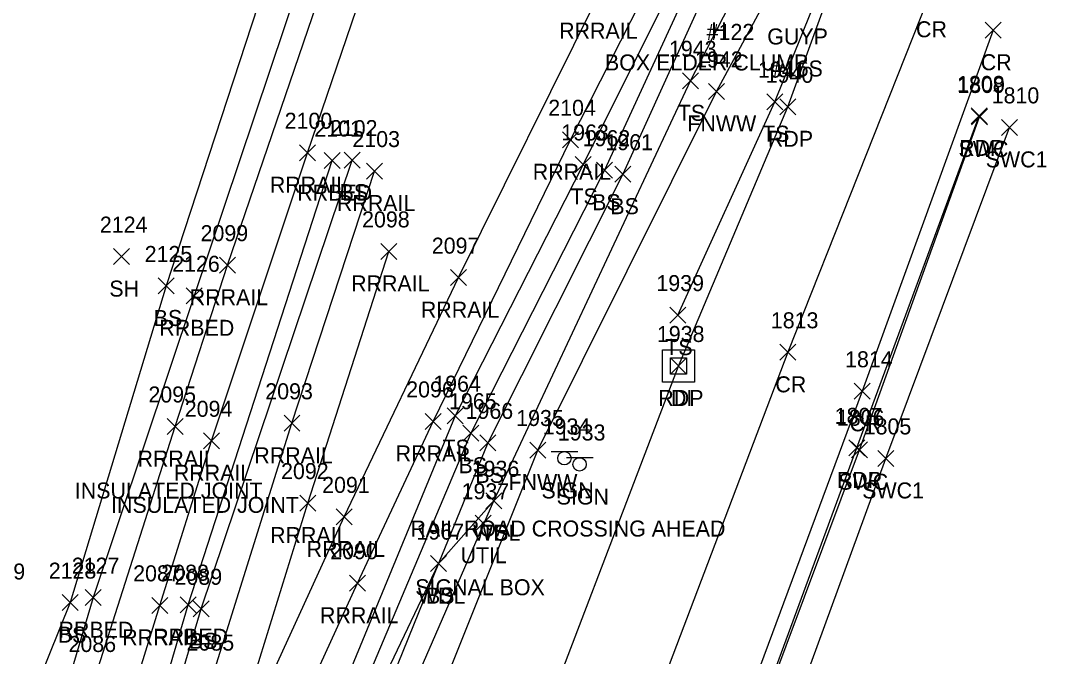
# Model space of a CAD drawing. Extents: x 1769141 to 1770817, y 735471 to 742405.
# Drawn here: x 1770272.6 to 1770400.9, y 742233 to 742312.5 of the extents above; entities that cross this region are included whole.
import ezdxf

# ---------------------------------------------------------------- set-up
doc = ezdxf.new("R2010")
doc.units = 0
for name, color, linetype in [('D_A', 7, 'Continuous'), ('D_I', 7, 'Continuous'), ('DS', 7, 'Continuous'), ('L_A', 7, 'Continuous'), ('L_C', 7, 'Continuous'), ('L_I', 7, 'Continuous'), ('L_TIC', 7, 'Continuous'), ('LAWA', 7, 'Continuous'), ('LELB', 7, 'Continuous'), ('LFNC', 7, 'Continuous'), ('P_A', 7, 'Continuous'), ('P_I', 7, 'Continuous'), ('P_TIC', 7, 'Continuous'), ('PET', 7, 'Continuous'), ('PRC', 7, 'Continuous'), ('R_A', 7, 'Continuous'), ('R_C', 7, 'Continuous'), ('R_I', 7, 'Continuous'), ('R_TIC', 7, 'Continuous'), ('RR', 7, 'Continuous'), ('RRB', 7, 'Continuous'), ('RSW', 7, 'Continuous'), ('S_A', 7, 'Continuous'), ('S_C', 7, 'Continuous'), ('S_I', 7, 'Continuous'), ('SSGN', 7, 'Continuous'), ('U_A', 7, 'Continuous'), ('U_C', 7, 'Continuous'), ('U_I', 7, 'Continuous'), ('UDEFAULT', 7, 'Continuous')]:
    doc.layers.add(name, color=color, linetype=linetype)

msp = doc.modelspace()

# ---------------------------------------------------------------- linework, layer by layer
at = {"layer": 'DS'}
for p, q in [((1770352.85, 742271.34), (1770356.85, 742271.34)), ((1770352.85, 742267.34), (1770352.85, 742271.34)), ((1770356.85, 742271.34), (1770356.85, 742267.34)), ((1770353.85, 742268.34), (1770353.85, 742270.34)), ((1770353.85, 742270.34), (1770355.85, 742270.34)), ((1770355.85, 742270.34), (1770355.85, 742268.34)), ((1770354.85, 742269.34), (1770354.85, 742269.34)), ((1770354.85, 742269.34), (1770354.85, 742269.34)), ((1770356.85, 742267.34), (1770352.85, 742267.34)), ((1770355.85, 742268.34), (1770353.85, 742268.34))]:
    msp.add_line(p, q, dxfattribs=at)
at = {"layer": 'L_TIC'}
for points in [[(1770355.36, 742303.98), (1770357.36, 742305.98)], [(1770357.36, 742303.98), (1770355.36, 742305.98)], [(1770358.62, 742302.65), (1770360.62, 742304.65)], [(1770360.62, 742302.65), (1770358.62, 742304.65)], [(1770365.91, 742301.37), (1770367.91, 742303.37)], [(1770367.91, 742301.37), (1770365.91, 742303.37)], [(1770313.05, 742294.07), (1770315.05, 742296.07)], [(1770315.05, 742294.07), (1770313.05, 742296.07)], [(1770341.94, 742293.53), (1770343.94, 742295.53)], [(1770343.94, 742293.53), (1770341.94, 742295.53)], [(1770344.62, 742292.81), (1770346.62, 742294.81)], [(1770346.62, 742292.81), (1770344.62, 742294.81)], [(1770346.9, 742292.31), (1770348.9, 742294.31)], [(1770348.9, 742292.31), (1770346.9, 742294.31)], [(1770284.21, 742282.01), (1770286.21, 742284.01)], [(1770286.21, 742282.01), (1770284.21, 742284.01)], [(1770289.81, 742278.34), (1770291.81, 742280.34)], [(1770291.81, 742278.34), (1770289.81, 742280.34)], [(1770353.8, 742274.7), (1770355.8, 742276.7)], [(1770355.8, 742274.7), (1770353.8, 742276.7)], [(1770325.94, 742262.13), (1770327.94, 742264.13)], [(1770327.94, 742262.13), (1770325.94, 742264.13)], [(1770327.91, 742259.94), (1770329.91, 742261.94)], [(1770329.91, 742259.94), (1770327.91, 742261.94)], [(1770330.03, 742258.73), (1770332.03, 742260.73)], [(1770332.03, 742258.73), (1770330.03, 742260.73)], [(1770336.26, 742257.84), (1770338.26, 742259.84)], [(1770338.26, 742257.84), (1770336.26, 742259.84)], [(1770330.76, 742251.5), (1770332.76, 742253.5)], [(1770332.76, 742251.5), (1770330.76, 742253.5)], [(1770330.76, 742251.5), (1770332.76, 742253.5)], [(1770332.76, 742251.5), (1770330.76, 742253.5)], [(1770323.85, 742243.64), (1770325.85, 742245.64)], [(1770325.85, 742243.64), (1770323.85, 742245.64)], [(1770323.85, 742243.64), (1770325.85, 742245.64)], [(1770325.85, 742243.64), (1770323.85, 742245.64)], [(1770277.82, 742238.77), (1770279.82, 742240.77)], [(1770279.82, 742238.77), (1770277.82, 742240.77)], [(1770294.2, 742238), (1770296.2, 742240)], [(1770296.2, 742238), (1770294.2, 742240)]]:
    msp.add_lwpolyline(points, dxfattribs=at)
at = {"layer": 'LAWA'}
msp.add_lwpolyline([(1770278.27, 742098.51), (1770292.63, 742130.75), (1770300.5, 742163.1), (1770310.78, 742196.92), (1770318.92, 742223), (1770331.76, 742252.5), (1770324.85, 742244.64), (1770302.11, 742188.56), (1770291.13, 742150.41), (1770288.91, 742136.29), (1770280.1, 742115.2), (1770273.51, 742098.5)], dxfattribs=at)
at = {"layer": 'LELB'}
for points in [[(1770332.23, 742396.99), (1770317.41, 742358.29), (1770305.3, 742323.67), (1770290.81, 742279.34), (1770278.82, 742239.77), (1770261.32, 742196.43), (1770254.37, 742156.7), (1770242.09, 742122.31), (1770234.14, 742089.37), (1770227.06, 742053.39), (1770219.68, 742019.63), (1770213.36, 741989.97), (1770210.16, 741976.3), (1770206.14, 741961.98)], [(1770380.12, 742366.91), (1770363.06, 742334.87), (1770342.94, 742294.53), (1770326.94, 742263.13), (1770309.84, 742221.71), (1770298.92, 742189.88), (1770289.69, 742167.82), (1770287.13, 742167.67), (1770285.1, 742161.65), (1770288.13, 742159.66), (1770284.67, 742135.52), (1770276.3, 742117.05), (1770269.66, 742099.09), (1770260.58, 742066.82), (1770250.33, 742031.54), (1770242.02, 742000.43), (1770236.09, 741978.68), (1770232.48, 741959.64)], [(1770381.35, 742366.29), (1770364.19, 742334.21), (1770345.62, 742293.81), (1770328.91, 742260.94), (1770312.07, 742221.07), (1770300.68, 742188.95), (1770290.98, 742164.79), (1770288.07, 742165.78), (1770286.6, 742162.38), (1770289.46, 742160.5), (1770286.3, 742134.62), (1770278.73, 742116.17), (1770272.1, 742098.75), (1770262.82, 742065.76), (1770253.59, 742031.78), (1770244.44, 742003.2), (1770237.54, 741978.15), (1770232.48, 741959.64)], [(1770383.19, 742365.59), (1770366.14, 742333.56), (1770347.9, 742293.31), (1770331.03, 742259.73), (1770324.85, 742244.64), (1770313.21, 742220.31)], [(1770331.76, 742252.5), (1770356.36, 742304.98), (1770372.15, 742335.65), (1770385.81, 742364.15)], [(1770354.8, 742275.7), (1770366.91, 742302.37), (1770378.08, 742330.08), (1770389.36, 742362.55)], [(1770255.17, 742093.88), (1770277.55, 742179.23), (1770295.2, 742239), (1770314.05, 742295.07)]]:
    msp.add_lwpolyline(points, dxfattribs=at)
at = {"layer": 'LFNC'}
msp.add_lwpolyline([(1770315.95, 742200.26), (1770321.95, 742220.54), (1770337.26, 742258.84), (1770359.62, 742303.65), (1770374.37, 742330.92)], dxfattribs=at)
at = {"layer": 'P_TIC'}
for points in [[(1770393.22, 742310.3), (1770395.22, 742312.3)], [(1770395.22, 742310.3), (1770393.22, 742312.3)], [(1770367.55, 742300.73), (1770369.55, 742302.73)], [(1770369.55, 742300.73), (1770367.55, 742302.73)], [(1770391.46, 742299.59), (1770393.46, 742301.59)], [(1770393.46, 742299.59), (1770391.46, 742301.59)], [(1770367.53, 742270.05), (1770369.53, 742272.05)], [(1770369.53, 742270.05), (1770367.53, 742272.05)], [(1770353.85, 742268.34), (1770355.85, 742270.34)], [(1770355.85, 742268.34), (1770353.85, 742270.34)], [(1770376.82, 742265.18), (1770378.82, 742267.18)], [(1770378.82, 742265.18), (1770376.82, 742267.18)], [(1770376.16, 742258.11), (1770378.16, 742260.11)], [(1770378.16, 742258.11), (1770376.16, 742260.11)]]:
    msp.add_lwpolyline(points, dxfattribs=at)
at = {"layer": 'PET'}
for points in [[(1770272.7, 742023.54), (1770282.64, 742061.02), (1770293.57, 742093.79), (1770304.4, 742127.71), (1770313.88, 742157.38), (1770333.72, 742213.99), (1770354.85, 742269.34), (1770368.55, 742301.73), (1770378.75, 742329.81), (1770392.05, 742361.37)], [(1770296.04, 742015.55), (1770303.14, 742042.61), (1770312.37, 742074.12), (1770317.15, 742087.84), (1770319.53, 742093.81), (1770328.4, 742119.72), (1770345.72, 742170.91), (1770359.21, 742210.32), (1770377.16, 742259.11), (1770392.46, 742300.59)]]:
    msp.add_lwpolyline(points, dxfattribs=at)
at = {"layer": 'PRC'}
for points in [[(1770386.13, 742315.42), (1770368.53, 742271.05), (1770352, 742227.48), (1770338.73, 742191.59), (1770324.94, 742150.68), (1770312.78, 742113.37), (1770302.28, 742081.69), (1770292.17, 742047.68), (1770283.01, 742015.74), (1770275.68, 741981.9), (1770269.49, 741954.54), (1770264.41, 741931.75), (1770261.81, 741920.34)], [(1770394.22, 742311.3), (1770377.82, 742266.18), (1770362.64, 742225.34), (1770348.95, 742186.97), (1770334.4, 742149.35), (1770325.02, 742114.58)]]:
    msp.add_lwpolyline(points, dxfattribs=at)
at = {"layer": 'R_TIC'}
for points in [[(1770391.51, 742299.46), (1770393.51, 742301.46)], [(1770393.51, 742299.46), (1770391.51, 742301.46)], [(1770395.24, 742298.16), (1770397.24, 742300.16)], [(1770397.24, 742298.16), (1770395.24, 742300.16)], [(1770340.35, 742296.61), (1770342.35, 742298.61)], [(1770342.35, 742296.61), (1770340.35, 742298.61)], [(1770307.47, 742294.99), (1770309.47, 742296.99)], [(1770309.47, 742294.99), (1770307.47, 742296.99)], [(1770310.55, 742294.01), (1770312.55, 742296.01)], [(1770312.55, 742294.01), (1770310.55, 742296.01)], [(1770315.86, 742292.7), (1770317.86, 742294.7)], [(1770317.86, 742292.7), (1770315.86, 742294.7)], [(1770317.64, 742282.66), (1770319.64, 742284.66)], [(1770319.64, 742282.66), (1770317.64, 742284.66)], [(1770297.46, 742280.94), (1770299.46, 742282.94)], [(1770299.46, 742280.94), (1770297.46, 742282.94)], [(1770326.36, 742279.38), (1770328.36, 742281.38)], [(1770328.36, 742279.38), (1770326.36, 742281.38)], [(1770293.31, 742277.11), (1770295.31, 742279.11)], [(1770295.31, 742277.11), (1770293.31, 742279.11)], [(1770323.21, 742261.42), (1770325.21, 742263.42)], [(1770325.21, 742261.42), (1770323.21, 742263.42)], [(1770290.93, 742260.78), (1770292.93, 742262.78)], [(1770292.93, 742260.78), (1770290.93, 742262.78)], [(1770305.54, 742261.18), (1770307.54, 742263.18)], [(1770307.54, 742261.18), (1770305.54, 742263.18)], [(1770295.47, 742258.99), (1770297.47, 742260.99)], [(1770297.47, 742258.99), (1770295.47, 742260.99)], [(1770376.48, 742257.88), (1770378.48, 742259.88)], [(1770378.48, 742257.88), (1770376.48, 742259.88)], [(1770379.8, 742256.79), (1770381.8, 742258.79)], [(1770381.8, 742256.79), (1770379.8, 742258.79)], [(1770307.51, 742251.21), (1770309.51, 742253.21)], [(1770309.51, 742251.21), (1770307.51, 742253.21)], [(1770312.08, 742249.48), (1770314.08, 742251.48)], [(1770314.08, 742249.48), (1770312.08, 742251.48)], [(1770313.75, 742241.2), (1770315.75, 742243.2)], [(1770315.75, 742241.2), (1770313.75, 742243.2)], [(1770280.7, 742239.39), (1770282.7, 742241.39)], [(1770282.7, 742239.39), (1770280.7, 742241.39)], [(1770289.02, 742238.43), (1770291.02, 742240.43)], [(1770291.02, 742238.43), (1770289.02, 742240.43)], [(1770292.54, 742238.51), (1770294.54, 742240.51)], [(1770294.54, 742238.51), (1770292.54, 742240.51)]]:
    msp.add_lwpolyline(points, dxfattribs=at)
at = {"layer": 'RR'}
for points in [[(1770228.86, 742035.21), (1770233.42, 742054.72), (1770238.03, 742073.49), (1770247.64, 742110.86), (1770257.95, 742148.59), (1770267.65, 742182.8), (1770278.27, 742218.42), (1770281.99, 742230.6), (1770291.93, 742261.78), (1770298.46, 742281.94), (1770310.78, 742317.95), (1770323.27, 742353.88), (1770336.53, 742389.56)], [(1770271.65, 742142.74), (1770276.09, 742158.59), (1770294.25, 742208.74), (1770297.09, 742215.37), (1770299.29, 742220.45), (1770313.08, 742250.48), (1770327.36, 742280.38), (1770344.65, 742315.25), (1770362.7, 742349.81), (1770381.95, 742383.73)], [(1770234.04, 742035.58), (1770238.5, 742054.13), (1770247.99, 742091.95), (1770252.55, 742109.85), (1770260.28, 742138.64), (1770270.31, 742174.37), (1770278.8, 742203.12), (1770290.02, 742239.43), (1770296.47, 742259.99), (1770308.47, 742295.99), (1770320.74, 742331.91), (1770333.76, 742367.71)], [(1770276.73, 742144.46), (1770284.44, 742168.76), (1770293.16, 742192.94), (1770306.05, 742223.24), (1770314.75, 742242.2), (1770324.21, 742262.42), (1770341.35, 742297.61), (1770358.95, 742332.23), (1770377.56, 742366.61)], [(1770212.41, 741956.11), (1770215.59, 741972.32), (1770224.21, 742004.12), (1770229.48, 742020.05), (1770231.83, 742026.33), (1770233.36, 742030.93), (1770234.9, 742035.43), (1770245.29, 742063.53), (1770258.11, 742100.47), (1770265.99, 742125.45), (1770269.66, 742137.91), (1770278.76, 742169.79), (1770287.08, 742199.09), (1770296.7, 742230.77), (1770306.54, 742262.18), (1770316.86, 742293.7)], [(1770216.86, 741956.06), (1770220.47, 741971.24), (1770224.73, 741988.15), (1770230.52, 742007.6), (1770241.28, 742038.61), (1770247.11, 742054.33), (1770252.93, 742070.06), (1770259.09, 742087.58), (1770269.15, 742118.93), (1770274.55, 742137.03), (1770276.73, 742144.46), (1770280.27, 742157.18), (1770289.26, 742188.86), (1770295.02, 742208.42), (1770297.09, 742215.37), (1770298.78, 742220.71), (1770308.51, 742252.21), (1770318.64, 742283.66)]]:
    msp.add_lwpolyline(points, dxfattribs=at)
at = {"layer": 'RRB'}
for points in [[(1770334.91, 742396.24), (1770320.98, 742356.43), (1770309.38, 742323.07), (1770294.31, 742278.11), (1770281.7, 742240.39), (1770267.62, 742193.22), (1770256.86, 742155.94), (1770246.81, 742120.87), (1770238.35, 742088.99), (1770231.63, 742060.85), (1770227.63, 742029.05), (1770215.73, 741989.64), (1770208.91, 741960.54)], [(1770219.87, 741959.41), (1770227.39, 741986.94), (1770232.28, 742006.89), (1770240.88, 742038.91), (1770254.48, 742094.84), (1770276.07, 742179.76), (1770293.54, 742239.51), (1770311.55, 742295.01)]]:
    msp.add_lwpolyline(points, dxfattribs=at)
at = {"layer": 'RSW'}
for points in [[(1770319.65, 742092.94), (1770328.45, 742119.75), (1770345.82, 742170.9), (1770359.28, 742210.21), (1770377.48, 742258.88), (1770392.51, 742300.46)], [(1770323.12, 742091.66), (1770336.55, 742131.82), (1770349.32, 742169.33), (1770362.98, 742209.08), (1770380.8, 742257.79), (1770396.24, 742299.16)]]:
    msp.add_lwpolyline(points, dxfattribs=at)
at = {"layer": 'SSGN'}
for p, q in [((1770338.94, 742258.65), (1770342.28, 742258.65)), ((1770340.59, 742257.81), (1770340.59, 742257.81)), ((1770340.85, 742257.89), (1770344.18, 742257.89)), ((1770342.49, 742257.05), (1770342.49, 742257.05))]:
    msp.add_line(p, q, dxfattribs=at)
for centre in [(1770340.59, 742257.81), (1770342.49, 742257.05)]:
    msp.add_circle(centre, 0.833, dxfattribs=at)
at = {"layer": 'UDEFAULT'}
for points in [[(1770329.44, 742248.69), (1770331.44, 742250.69)], [(1770331.44, 742248.69), (1770329.44, 742250.69)]]:
    msp.add_lwpolyline(points, dxfattribs=at)

# ---------------------------------------------------------------- texts
at = {"layer": 'D_A'}
msp.add_text('DI', height=2, dxfattribs=at).set_placement((1770353.91, 742264.34))
at = {"layer": 'D_I'}
msp.add_text('1938', height=2, dxfattribs=at).set_placement((1770352.16, 742272.34))
at = {"layer": 'L_A'}
for s, p in [('H', (1770358.96, 742310.27)), ('TS', (1770354.77, 742299.98)), ('FNWW', (1770355.97, 742298.65)), ('TS', (1770365.32, 742297.37)), ('BS', (1770312.49, 742290.07)), ('TS', (1770341.35, 742289.53)), ('BS', (1770344.06, 742288.81)), ('BS', (1770346.34, 742288.31)), ('SH', (1770283.7, 742278.01)), ('BS', (1770289.25, 742274.34)), ('TS', (1770353.21, 742270.7)), ('TS', (1770325.35, 742258.13)), ('BS', (1770327.35, 742255.94)), ('BS', (1770329.47, 742254.73)), ('FNWW', (1770333.61, 742253.84)), ('WDL', (1770329.17, 742247.5)), ('TS', (1770330.17, 742247.5)), ('WDL', (1770322.27, 742239.64)), ('BS', (1770323.29, 742239.64)), ('BS', (1770277.26, 742234.77)), ('BS', (1770293.64, 742234))]:
    msp.add_text(s, height=2, dxfattribs=at).set_placement(p)
at = {"layer": 'L_C'}
msp.add_text('BOX ELDER CLUMP', height=2, dxfattribs=at).set_placement((1770345.67, 742306.27))
at = {"layer": 'L_I'}
for s, p in [('1943', (1770353.67, 742307.98)), ('1942', (1770356.93, 742306.65)), ('1941', (1770364.79, 742305.37)), ('2102', (1770311.28, 742298.07)), ('1963', (1770340.2, 742297.53)), ('1962', (1770342.88, 742296.81)), ('1961', (1770345.72, 742296.31)), ('2124', (1770282.52, 742286.01)), ('2125', (1770288.12, 742282.34)), ('1939', (1770352.1, 742278.7)), ('1964', (1770324.2, 742266.13)), ('1965', (1770326.17, 742263.94)), ('1966', (1770328.24, 742262.73)), ('1935', (1770334.57, 742261.84)), ('1936', (1770329.01, 742255.5)), ('1936', (1770329.01, 742255.5)), ('1967', (1770322.11, 742247.64)), ('1967', (1770322.11, 742247.64)), ('2129', (1770267.23, 742242.66)), ('2128', (1770276.13, 742242.77)), ('2089', (1770291.86, 742242))]:
    msp.add_text(s, height=2, dxfattribs=at).set_placement(p)
at = {"layer": 'P_A'}
for s, p in [('CR', (1770384.56, 742310.42)), ('CR', (1770392.65, 742306.3)), ('RDP', (1770366.04, 742296.73)), ('RDP', (1770389.95, 742295.59)), ('CR', (1770366.97, 742266.05)), ('RDP', (1770352.34, 742264.34)), ('CR', (1770376.25, 742261.18)), ('RDP', (1770374.65, 742254.11))]:
    msp.add_text(s, height=2, dxfattribs=at).set_placement(p)
at = {"layer": 'P_I'}
for s, p in [('1940', (1770365.77, 742304.73)), ('1808', (1770389.69, 742303.59)), ('1813', (1770366.41, 742274.05)), ('1938', (1770352.16, 742272.34)), ('1814', (1770375.69, 742269.18)), ('1807', (1770374.39, 742262.11))]:
    msp.add_text(s, height=2, dxfattribs=at).set_placement(p)
at = {"layer": 'R_A'}
for s, p in [('RRRAIL', (1770339.94, 742310.25)), ('SWC', (1770389.87, 742295.46)), ('SWC1', (1770393.27, 742294.16)), ('RRRAIL', (1770336.64, 742292.61)), ('RRRAIL', (1770303.77, 742290.99)), ('RRBED', (1770307.19, 742290.01)), ('RRRAIL', (1770312.15, 742288.7)), ('RRRAIL', (1770313.93, 742278.66)), ('RRRAIL', (1770293.75, 742276.94)), ('RRRAIL', (1770322.65, 742275.38)), ('RRBED', (1770289.96, 742273.11)), ('RRRAIL', (1770319.5, 742257.42)), ('RRRAIL', (1770287.22, 742256.78)), ('RRRAIL', (1770301.83, 742257.18)), ('RRRAIL', (1770291.76, 742254.99)), ('SWC', (1770374.84, 742253.88)), ('SWC1', (1770377.83, 742252.79)), ('RRRAIL', (1770303.8, 742247.21)), ('RRRAIL', (1770308.37, 742245.48)), ('RRRAIL', (1770310.04, 742237.2)), ('RRBED', (1770277.35, 742235.39)), ('RRRAIL', (1770285.31, 742234.43)), ('RRBED', (1770289.19, 742234.51))]:
    msp.add_text(s, height=2, dxfattribs=at).set_placement(p)
at = {"layer": 'R_C'}
for p in [(1770279.39, 742252.78), (1770283.92, 742250.99)]:
    msp.add_text('INSULATED JOINT', height=2, dxfattribs=at).set_placement(p)
at = {"layer": 'R_I'}
for s, p in [('1809', (1770389.73, 742303.46)), ('1810', (1770394.02, 742302.16)), ('2104', (1770338.58, 742300.61)), ('2100', (1770305.62, 742298.99)), ('2101', (1770309.34, 742298.01)), ('2103', (1770314.09, 742296.7)), ('2098', (1770315.3, 742286.66)), ('2099', (1770295.11, 742284.94)), ('2097', (1770324.02, 742283.38)), ('2126', (1770291.56, 742281.11)), ('2093', (1770303.2, 742265.18)), ('2096', (1770320.82, 742265.42)), ('2095', (1770288.59, 742264.78)), ('2094', (1770293.13, 742262.99)), ('1806', (1770374.66, 742261.88)), ('1805', (1770378.02, 742260.79)), ('2092', (1770305.17, 742255.21)), ('2091', (1770310.31, 742253.48)), ('2090', (1770311.32, 742245.2)), ('2127', (1770279.01, 742243.39)), ('2087', (1770286.68, 742242.43)), ('2088', (1770290.2, 742242.51)), ('2086', (1770278.6, 742233.6)), ('2085', (1770293.36, 742233.77))]:
    msp.add_text(s, height=2, dxfattribs=at).set_placement(p)
at = {"layer": 'S_A'}
for p in [(1770337.73, 742252.79), (1770339.63, 742252.03)]:
    msp.add_text('SIGN', height=2, dxfattribs=at).set_placement(p)
at = {"layer": 'S_C'}
msp.add_text('RAIL ROAD CROSSING AHEAD', height=2, dxfattribs=at).set_placement((1770321.35, 742248.03))
at = {"layer": 'S_I'}
for s, p in [('1934', (1770337.88, 742260.79)), ('1933', (1770339.78, 742260.03))]:
    msp.add_text(s, height=2, dxfattribs=at).set_placement(p)
at = {"layer": 'U_A'}
for s, p in [('GUYP', (1770365.96, 742309.52)), ('UTIL', (1770327.61, 742244.69))]:
    msp.add_text(s, height=2, dxfattribs=at).set_placement(p)
at = {"layer": 'U_C'}
for s, p in [('#122', (1770358.39, 742310.09)), ('#16S', (1770366.66, 742305.52)), ('SIGNAL BOX', (1770321.95, 742240.69))]:
    msp.add_text(s, height=2, dxfattribs=at).set_placement(p)
at = {"layer": 'U_I'}
msp.add_text('1937', height=2, dxfattribs=at).set_placement((1770327.75, 742252.69))

doc.saveas('drawing.dxf')
